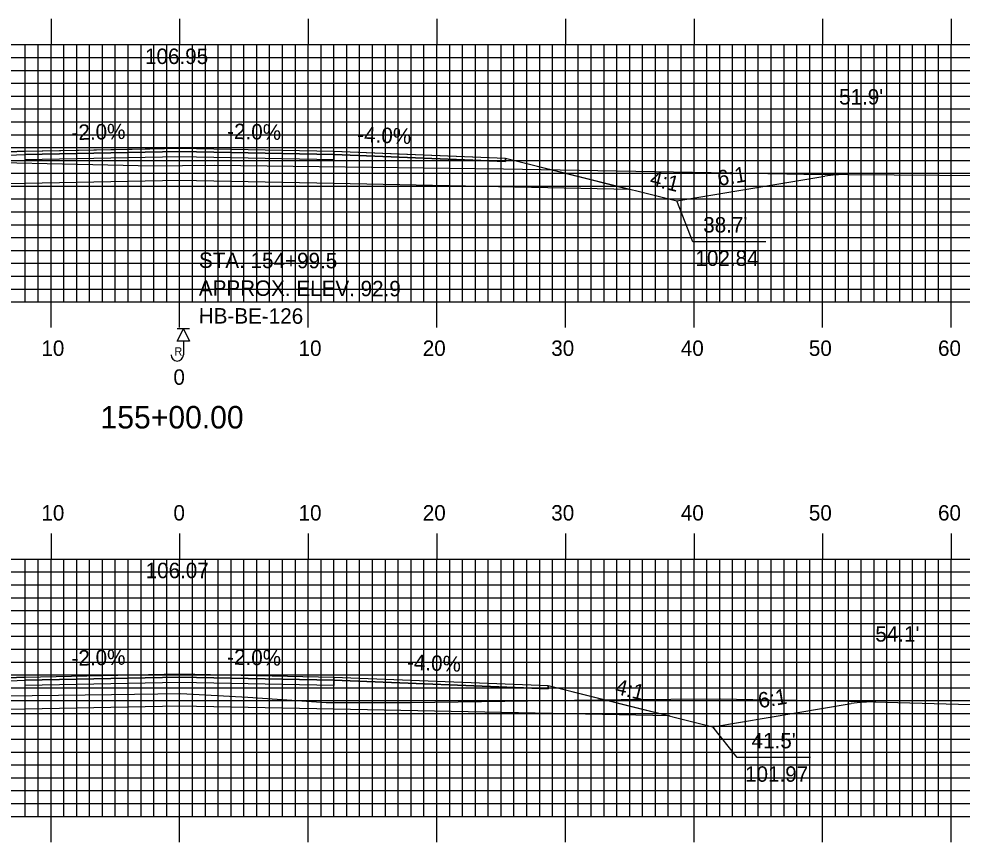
# Model space of a CAD drawing. Extents: x 1779106 to 1779449, y 442591 to 442811.
# Drawn here: x 1779258.8 to 1779332.2, y 442646.7 to 442710.7 of the extents above; entities that cross this region are included whole.
import ezdxf

# ---------------------------------------------------------------- set-up
doc = ezdxf.new("R2010")
doc.units = 0
for name, color, linetype in [('ANNOTATION', 7, 'Continuous'), ('BORING - REFUSAL', 7, 'Continuous'), ('D_Roadway_Centerline', 7, 'Continuous'), ('D_Roadway_Centerline_Text', 7, 'Continuous'), ('D_Roadway_Edge_Shoulder', 7, 'Continuous'), ('D_Roadway_Edge_TW', 7, 'Continuous'), ('D_Roadway_Pavement', 7, 'Continuous'), ('D_Roadway_SlopeLines', 7, 'Continuous'), ('D_Roadway_SubGrade', 7, 'Continuous'), ('D_Text_Standard', 7, 'Continuous'), ('H_V ANNOTATION', 7, 'Continuous'), ('MAJOR', 7, 'Continuous'), ('MINOR', 7, 'Continuous'), ('S_Roadway_Centerline', 7, 'Continuous')]:
    doc.layers.add(name, color=color, linetype=linetype)

msp = doc.modelspace()

# ---------------------------------------------------------------- linework, layer by layer
at = {"layer": 'ANNOTATION'}
for points in [[(1779316.925, 442693.332), (1779311.233, 442693.332), (1779309.983, 442696.509)], [(1779320.388, 442653.229), (1779314.696, 442653.229), (1779312.783, 442655.634)]]:
    msp.add_lwpolyline(points, dxfattribs=at)
at = {"layer": 'BORING - REFUSAL'}
for p, q in [((1779272.109, 442686.565), (1779271.149, 442686.565)), ((1779271.629, 442685.606), (1779271.629, 442684.547))]:
    msp.add_line(p, q, dxfattribs=at)
msp.add_lwpolyline([(1779271.629, 442686.565), (1779272.109, 442685.606), (1779271.149, 442685.606)], close=True, dxfattribs=at)
msp.add_arc((1779271.144, 442684.547), 0.485, 180, 0, dxfattribs=at)
at = {"layer": 'D_Roadway_Centerline'}
for points in [[(1779212.709, 442700.252), (1779213.959, 442700.189), (1779215.209, 442700.084), (1779216.459, 442699.938), (1779217.709, 442699.75), (1779219.392, 442699.47), (1779237.155, 442696.509), (1779237.6, 442696.621), (1779241.155, 442697.509), (1779251.329, 442700.052), (1779255.495, 442700.219), (1779259.329, 442700.372), (1779269.01, 442700.566), (1779271.329, 442700.612), (1779283.329, 442700.372), (1779289, 442700.145), (1779296.662, 442699.839), (1779306.371, 442697.412)], [(1779215.099, 442658.85), (1779216.348, 442658.843), (1779217.599, 442658.779), (1779217.756, 442658.764), (1779218.848, 442658.656), (1779220.098, 442658.477), (1779222.988, 442657.996), (1779237.155, 442655.634), (1779241.155, 442656.634), (1779251.329, 442659.177), (1779259.33, 442659.497), (1779271.329, 442659.737), (1779283.329, 442659.497), (1779299.996, 442658.831), (1779307.083, 442657.059), (1779309.415, 442656.476)]]:
    msp.add_lwpolyline(points, dxfattribs=at)
at = {"layer": 'D_Roadway_Edge_Shoulder'}
for points in [[(1779259.329, 442700.372), (1779251.329, 442700.052), (1779251.329, 442699.802), (1779259.329, 442700.122)], [(1779283.329, 442700.372), (1779296.662, 442699.839), (1779296.662, 442699.589), (1779283.329, 442700.122)], [(1779259.33, 442659.497), (1779251.329, 442659.177), (1779251.329, 442658.927), (1779259.33, 442659.247)], [(1779283.329, 442659.497), (1779299.996, 442658.831), (1779299.996, 442658.581), (1779283.329, 442659.247)]]:
    msp.add_lwpolyline(points, close=True, dxfattribs=at)
at = {"layer": 'D_Roadway_Edge_TW'}
for points in [[(1779259.329, 442700.122), (1779259.329, 442700.372), (1779271.329, 442700.612), (1779283.329, 442700.372), (1779283.329, 442700.122), (1779271.329, 442700.362)], [(1779259.33, 442659.247), (1779259.33, 442659.497), (1779271.329, 442659.737), (1779283.329, 442659.497), (1779283.329, 442659.247), (1779271.329, 442659.487)]]:
    msp.add_lwpolyline(points, close=True, dxfattribs=at)
at = {"layer": 'D_Roadway_Pavement'}
for points in [[(1779259.329, 442699.706), (1779259.329, 442700.122), (1779271.329, 442700.362), (1779283.329, 442700.122), (1779283.329, 442699.706), (1779271.329, 442699.946)], [(1779259.33, 442658.831), (1779259.33, 442659.247), (1779271.329, 442659.487), (1779283.329, 442659.247), (1779283.329, 442658.831), (1779271.329, 442659.071)]]:
    msp.add_lwpolyline(points, close=True, dxfattribs=at)
at = {"layer": 'D_Roadway_SlopeLines'}
msp.add_line((1779309.983, 442696.509), (1779321.501, 442698.429), dxfattribs=at)
for points in [[(1779296.662, 442699.839), (1779309.983, 442696.509)], [(1779299.996, 442658.831), (1779312.785, 442655.636)], [(1779312.783, 442655.634), (1779323.545, 442657.428)]]:
    msp.add_lwpolyline(points, dxfattribs=at)
for centre, start, end in [((1779323.145, 442688.565), 89.55743, 99.46232), ((1779325.188, 442647.564), 88.43894, 99.46085)]:
    msp.add_arc(centre, 10, start, end, dxfattribs=at)
at = {"layer": 'D_Roadway_SubGrade'}
for points in [[(1779259.329, 442697.872), (1779241.155, 442697.509), (1779251.329, 442700.052), (1779251.329, 442699.802), (1779259.329, 442700.122), (1779271.329, 442700.362), (1779283.329, 442700.122), (1779296.662, 442699.589), (1779296.662, 442699.839), (1779306.371, 442697.412), (1779283.329, 442697.872), (1779271.329, 442698.112)], [(1779259.33, 442656.997), (1779241.155, 442656.634), (1779251.329, 442659.177), (1779251.329, 442658.927), (1779259.33, 442659.247), (1779271.329, 442659.487), (1779283.329, 442659.247), (1779299.996, 442658.581), (1779299.996, 442658.831), (1779309.415, 442656.476), (1779283.329, 442656.997), (1779271.329, 442657.237)]]:
    msp.add_lwpolyline(points, close=True, dxfattribs=at)
at = {"layer": 'MAJOR'}
for p, q in [((1779261.329, 442710.669), (1779261.329, 442708.665)), ((1779271.329, 442710.669), (1779271.329, 442708.665)), ((1779281.329, 442710.669), (1779281.329, 442708.665)), ((1779291.329, 442710.669), (1779291.329, 442708.665)), ((1779301.329, 442710.669), (1779301.329, 442708.665)), ((1779311.329, 442710.669), (1779311.329, 442708.665)), ((1779321.329, 442710.669), (1779321.329, 442708.665)), ((1779331.329, 442710.669), (1779331.329, 442708.665)), ((1779131.329, 442708.665), (1779411.329, 442708.665)), ((1779131.329, 442708.665), (1779411.329, 442708.665)), ((1779261.329, 442688.665), (1779261.329, 442708.665)), ((1779271.329, 442688.665), (1779271.329, 442708.665)), ((1779281.329, 442688.665), (1779281.329, 442708.665)), ((1779291.329, 442688.665), (1779291.329, 442708.665)), ((1779301.329, 442688.665), (1779301.329, 442708.665)), ((1779311.329, 442688.665), (1779311.329, 442708.665)), ((1779321.329, 442688.665), (1779321.329, 442708.665)), ((1779331.329, 442688.665), (1779331.329, 442708.665)), ((1779131.329, 442703.665), (1779411.329, 442703.665)), ((1779131.956, 442698.665), (1779411.956, 442698.665)), ((1779131.329, 442693.665), (1779411.329, 442693.665)), ((1779131.329, 442688.665), (1779411.329, 442688.665)), ((1779131.329, 442688.665), (1779411.329, 442688.665)), ((1779261.329, 442686.661), (1779261.329, 442688.665)), ((1779271.329, 442686.661), (1779271.329, 442688.665)), ((1779281.329, 442686.661), (1779281.329, 442688.665)), ((1779291.329, 442686.661), (1779291.329, 442688.665)), ((1779301.329, 442686.661), (1779301.329, 442688.665)), ((1779311.329, 442686.661), (1779311.329, 442688.665)), ((1779321.329, 442686.661), (1779321.329, 442688.665)), ((1779331.329, 442686.661), (1779331.329, 442688.665)), ((1779261.329, 442670.669), (1779261.329, 442668.665)), ((1779271.329, 442670.669), (1779271.329, 442668.665)), ((1779281.329, 442670.669), (1779281.329, 442668.665)), ((1779291.329, 442670.669), (1779291.329, 442668.665)), ((1779301.329, 442670.669), (1779301.329, 442668.665)), ((1779311.329, 442670.669), (1779311.329, 442668.665)), ((1779321.329, 442670.669), (1779321.329, 442668.665)), ((1779331.329, 442670.669), (1779331.329, 442668.665)), ((1779131.329, 442668.665), (1779411.329, 442668.665)), ((1779131.329, 442668.665), (1779411.329, 442668.665)), ((1779261.329, 442648.665), (1779261.329, 442668.665)), ((1779271.329, 442648.665), (1779271.329, 442668.665)), ((1779281.329, 442648.665), (1779281.329, 442668.665)), ((1779291.329, 442648.665), (1779291.329, 442668.665)), ((1779301.329, 442648.665), (1779301.329, 442668.665)), ((1779311.329, 442648.665), (1779311.329, 442668.665)), ((1779321.329, 442648.665), (1779321.329, 442668.665)), ((1779331.329, 442648.665), (1779331.329, 442668.665)), ((1779131.329, 442663.665), (1779411.329, 442663.665)), ((1779131.329, 442658.665), (1779411.329, 442658.665)), ((1779131.329, 442653.665), (1779411.329, 442653.665)), ((1779131.329, 442648.665), (1779411.329, 442648.665)), ((1779131.329, 442648.665), (1779411.329, 442648.665)), ((1779261.329, 442646.661), (1779261.329, 442648.665)), ((1779271.329, 442646.661), (1779271.329, 442648.665)), ((1779281.329, 442646.661), (1779281.329, 442648.665)), ((1779291.329, 442646.661), (1779291.329, 442648.665)), ((1779301.329, 442646.661), (1779301.329, 442648.665)), ((1779311.329, 442646.661), (1779311.329, 442648.665)), ((1779321.329, 442646.661), (1779321.329, 442648.665)), ((1779331.329, 442646.661), (1779331.329, 442648.665))]:
    msp.add_line(p, q, dxfattribs=at)
at = {"layer": 'MINOR'}
for p, q in [((1779259.329, 442688.665), (1779259.329, 442708.665)), ((1779260.329, 442688.665), (1779260.329, 442708.665)), ((1779262.329, 442688.665), (1779262.329, 442708.665)), ((1779263.329, 442688.665), (1779263.329, 442708.665)), ((1779264.329, 442688.665), (1779264.329, 442708.665)), ((1779265.329, 442688.665), (1779265.329, 442708.665)), ((1779266.329, 442688.665), (1779266.329, 442708.665)), ((1779267.329, 442688.665), (1779267.329, 442708.665)), ((1779268.329, 442688.665), (1779268.329, 442708.665)), ((1779269.329, 442688.665), (1779269.329, 442708.665)), ((1779270.329, 442688.665), (1779270.329, 442708.665)), ((1779272.329, 442688.665), (1779272.329, 442708.665)), ((1779273.329, 442688.665), (1779273.329, 442708.665)), ((1779274.329, 442688.665), (1779274.329, 442708.665)), ((1779275.329, 442688.665), (1779275.329, 442708.665)), ((1779276.329, 442688.665), (1779276.329, 442708.665)), ((1779277.329, 442688.665), (1779277.329, 442708.665)), ((1779278.329, 442688.665), (1779278.329, 442708.665)), ((1779279.329, 442688.665), (1779279.329, 442708.665)), ((1779280.329, 442688.665), (1779280.329, 442708.665)), ((1779282.329, 442688.665), (1779282.329, 442708.665)), ((1779283.329, 442688.665), (1779283.329, 442708.665)), ((1779284.329, 442688.665), (1779284.329, 442708.665)), ((1779285.329, 442688.665), (1779285.329, 442708.665)), ((1779286.329, 442688.665), (1779286.329, 442708.665)), ((1779287.329, 442688.665), (1779287.329, 442708.665)), ((1779288.329, 442688.665), (1779288.329, 442708.665)), ((1779289.329, 442688.665), (1779289.329, 442708.665)), ((1779290.329, 442688.665), (1779290.329, 442708.665)), ((1779292.329, 442688.665), (1779292.329, 442708.665)), ((1779293.329, 442688.665), (1779293.329, 442708.665)), ((1779294.329, 442688.665), (1779294.329, 442708.665)), ((1779295.329, 442688.665), (1779295.329, 442708.665)), ((1779296.329, 442688.665), (1779296.329, 442708.665)), ((1779297.329, 442688.665), (1779297.329, 442708.665)), ((1779298.329, 442688.665), (1779298.329, 442708.665)), ((1779299.329, 442688.665), (1779299.329, 442708.665)), ((1779300.329, 442688.665), (1779300.329, 442708.665)), ((1779302.329, 442688.665), (1779302.329, 442708.665)), ((1779303.329, 442688.665), (1779303.329, 442708.665)), ((1779304.329, 442688.665), (1779304.329, 442708.665)), ((1779305.329, 442688.665), (1779305.329, 442708.665)), ((1779306.329, 442688.665), (1779306.329, 442708.665)), ((1779307.329, 442688.665), (1779307.329, 442708.665)), ((1779308.329, 442688.665), (1779308.329, 442708.665)), ((1779309.329, 442688.665), (1779309.329, 442708.665)), ((1779310.329, 442688.665), (1779310.329, 442708.665)), ((1779312.329, 442688.665), (1779312.329, 442708.665)), ((1779313.329, 442688.665), (1779313.329, 442708.665)), ((1779314.329, 442688.665), (1779314.329, 442708.665)), ((1779315.329, 442688.665), (1779315.329, 442708.665)), ((1779316.329, 442688.665), (1779316.329, 442708.665)), ((1779317.329, 442688.665), (1779317.329, 442708.665)), ((1779318.329, 442688.665), (1779318.329, 442708.665)), ((1779319.329, 442688.665), (1779319.329, 442708.665)), ((1779320.329, 442688.665), (1779320.329, 442708.665)), ((1779322.329, 442688.665), (1779322.329, 442708.665)), ((1779323.329, 442688.665), (1779323.329, 442708.665)), ((1779324.329, 442688.665), (1779324.329, 442708.665)), ((1779325.329, 442688.665), (1779325.329, 442708.665)), ((1779326.329, 442688.665), (1779326.329, 442708.665)), ((1779327.329, 442688.665), (1779327.329, 442708.665)), ((1779328.329, 442688.665), (1779328.329, 442708.665)), ((1779329.329, 442688.665), (1779329.329, 442708.665)), ((1779330.329, 442688.665), (1779330.329, 442708.665)), ((1779131.329, 442707.665), (1779411.329, 442707.665)), ((1779131.329, 442706.665), (1779411.329, 442706.665)), ((1779131.329, 442705.665), (1779411.329, 442705.665)), ((1779131.329, 442704.665), (1779411.329, 442704.665)), ((1779131.329, 442702.665), (1779411.329, 442702.665)), ((1779131.329, 442701.665), (1779411.329, 442701.665)), ((1779131.329, 442700.665), (1779411.329, 442700.665)), ((1779131.329, 442699.665), (1779411.329, 442699.665)), ((1779131.329, 442697.665), (1779411.329, 442697.665)), ((1779131.329, 442696.665), (1779411.329, 442696.665)), ((1779131.329, 442695.665), (1779411.329, 442695.665)), ((1779131.329, 442694.665), (1779411.329, 442694.665)), ((1779131.329, 442692.665), (1779411.329, 442692.665)), ((1779131.329, 442691.665), (1779411.329, 442691.665)), ((1779131.329, 442690.665), (1779411.329, 442690.665)), ((1779131.329, 442689.665), (1779411.329, 442689.665)), ((1779259.329, 442648.665), (1779259.329, 442668.665)), ((1779260.329, 442648.665), (1779260.329, 442668.665)), ((1779262.329, 442648.665), (1779262.329, 442668.665)), ((1779263.329, 442648.665), (1779263.329, 442668.665)), ((1779264.329, 442648.665), (1779264.329, 442668.665)), ((1779265.329, 442648.665), (1779265.329, 442668.665)), ((1779266.329, 442648.665), (1779266.329, 442668.665)), ((1779267.329, 442648.665), (1779267.329, 442668.665)), ((1779268.329, 442648.665), (1779268.329, 442668.665)), ((1779269.329, 442648.665), (1779269.329, 442668.665)), ((1779270.329, 442648.665), (1779270.329, 442668.665)), ((1779272.329, 442648.665), (1779272.329, 442668.665)), ((1779273.329, 442648.665), (1779273.329, 442668.665)), ((1779274.329, 442648.665), (1779274.329, 442668.665)), ((1779275.329, 442648.665), (1779275.329, 442668.665)), ((1779276.329, 442648.665), (1779276.329, 442668.665)), ((1779277.329, 442648.665), (1779277.329, 442668.665)), ((1779278.329, 442648.665), (1779278.329, 442668.665)), ((1779279.329, 442648.665), (1779279.329, 442668.665)), ((1779280.329, 442648.665), (1779280.329, 442668.665)), ((1779282.329, 442648.665), (1779282.329, 442668.665)), ((1779283.329, 442648.665), (1779283.329, 442668.665)), ((1779284.329, 442648.665), (1779284.329, 442668.665)), ((1779285.329, 442648.665), (1779285.329, 442668.665)), ((1779286.329, 442648.665), (1779286.329, 442668.665)), ((1779287.329, 442648.665), (1779287.329, 442668.665)), ((1779288.329, 442648.665), (1779288.329, 442668.665)), ((1779289.329, 442648.665), (1779289.329, 442668.665)), ((1779290.329, 442648.665), (1779290.329, 442668.665)), ((1779292.329, 442648.665), (1779292.329, 442668.665)), ((1779293.329, 442648.665), (1779293.329, 442668.665)), ((1779294.329, 442648.665), (1779294.329, 442668.665)), ((1779295.329, 442648.665), (1779295.329, 442668.665)), ((1779296.329, 442648.665), (1779296.329, 442668.665)), ((1779297.329, 442648.665), (1779297.329, 442668.665)), ((1779298.329, 442648.665), (1779298.329, 442668.665)), ((1779299.329, 442648.665), (1779299.329, 442668.665)), ((1779300.329, 442648.665), (1779300.329, 442668.665)), ((1779302.329, 442648.665), (1779302.329, 442668.665)), ((1779303.329, 442648.665), (1779303.329, 442668.665)), ((1779304.329, 442648.665), (1779304.329, 442668.665)), ((1779305.329, 442648.665), (1779305.329, 442668.665)), ((1779306.329, 442648.665), (1779306.329, 442668.665)), ((1779307.329, 442648.665), (1779307.329, 442668.665)), ((1779308.329, 442648.665), (1779308.329, 442668.665)), ((1779309.329, 442648.665), (1779309.329, 442668.665)), ((1779310.329, 442648.665), (1779310.329, 442668.665)), ((1779312.329, 442648.665), (1779312.329, 442668.665)), ((1779313.329, 442648.665), (1779313.329, 442668.665)), ((1779314.329, 442648.665), (1779314.329, 442668.665)), ((1779315.329, 442648.665), (1779315.329, 442668.665)), ((1779316.329, 442648.665), (1779316.329, 442668.665)), ((1779317.329, 442648.665), (1779317.329, 442668.665)), ((1779318.329, 442648.665), (1779318.329, 442668.665)), ((1779319.329, 442648.665), (1779319.329, 442668.665)), ((1779320.329, 442648.665), (1779320.329, 442668.665)), ((1779322.329, 442648.665), (1779322.329, 442668.665)), ((1779323.329, 442648.665), (1779323.329, 442668.665)), ((1779324.329, 442648.665), (1779324.329, 442668.665)), ((1779325.329, 442648.665), (1779325.329, 442668.665)), ((1779326.329, 442648.665), (1779326.329, 442668.665)), ((1779327.329, 442648.665), (1779327.329, 442668.665)), ((1779328.329, 442648.665), (1779328.329, 442668.665)), ((1779329.329, 442648.665), (1779329.329, 442668.665)), ((1779330.329, 442648.665), (1779330.329, 442668.665)), ((1779131.329, 442667.665), (1779411.329, 442667.665)), ((1779131.329, 442666.665), (1779411.329, 442666.665)), ((1779131.329, 442665.665), (1779411.329, 442665.665)), ((1779131.329, 442664.665), (1779411.329, 442664.665)), ((1779131.329, 442662.665), (1779411.329, 442662.665)), ((1779131.329, 442661.665), (1779411.329, 442661.665)), ((1779131.329, 442660.665), (1779411.329, 442660.665)), ((1779131.329, 442659.665), (1779411.329, 442659.665)), ((1779131.329, 442657.665), (1779411.329, 442657.665)), ((1779131.329, 442656.665), (1779411.329, 442656.665)), ((1779131.329, 442655.665), (1779411.329, 442655.665)), ((1779131.329, 442654.665), (1779411.329, 442654.665)), ((1779131.329, 442652.665), (1779411.329, 442652.665)), ((1779131.329, 442651.665), (1779411.329, 442651.665)), ((1779131.329, 442650.665), (1779411.329, 442650.665)), ((1779131.329, 442649.665), (1779411.329, 442649.665))]:
    msp.add_line(p, q, dxfattribs=at)
at = {"layer": 'S_Roadway_Centerline'}
for points in [[(1779204.871, 442700.576), (1779214.722, 442700.169), (1779223.429, 442700.124), (1779228.785, 442700.064), (1779247.046, 442699.731), (1779248.885, 442699.733), (1779250.388, 442699.649), (1779269.305, 442699.254), (1779271.551, 442699.27), (1779274.069, 442699.291), (1779294.366, 442699.041), (1779296.506, 442699.002), (1779318.544, 442698.617), (1779319.857, 442698.591), (1779340.931, 442698.428)], [(1779190.733, 442658.669), (1779209.659, 442658.921), (1779213.36, 442658.816), (1779217.296, 442658.895), (1779225.136, 442658.872), (1779231.553, 442658.528), (1779242.659, 442658.056), (1779248.767, 442658.064), (1779253.673, 442657.985), (1779266.039, 442658.147), (1779271.426, 442658.224), (1779276.627, 442657.928), (1779282.717, 442657.528), (1779289.372, 442657.506), (1779305.664, 442657.756), (1779313.385, 442657.809), (1779317.147, 442657.713), (1779321.517, 442657.667), (1779341.306, 442657.128)]]:
    msp.add_lwpolyline(points, dxfattribs=at)

# ---------------------------------------------------------------- texts
at = {"layer": 'ANNOTATION'}
for s, rotation, p in [('-2.0%', 1.14576, (1779262.935, 442701.245)), ('-2.0%', 358.85424, (1779275.015, 442701.339)), ('-4.0%', 357.70926, (1779285.121, 442701.102)), ('6:1', 9.46012, (1779313.259, 442697.669)), ('4:1', 345.96306, (1779307.824, 442697.75)), ('-2.0%', 1.14582, (1779262.936, 442660.37)), ('-2.0%', 358.85424, (1779275.015, 442660.464)), ('-4.0%', 357.70947, (1779288.993, 442660.072)), ('4:1', 345.96523, (1779305.125, 442658.215)), ('6:1', 9.46087, (1779316.421, 442657.068))]:
    msp.add_text(s, height=1.2, rotation=rotation, dxfattribs=at).set_placement(p)
for s, p in [("38.7'", (1779312.043, 442694.059)), ('102.84', (1779311.438, 442691.459)), ("41.5'", (1779315.805, 442653.955)), ('101.97', (1779315.297, 442651.355))]:
    msp.add_text(s, height=1.2, dxfattribs=at).set_placement(p)
at = {"layer": 'BORING - REFUSAL'}
for s, p in [('STA. 154+99.5', (1779272.833, 442691.308)), ('APPROX. ELEV. 92.9', (1779272.826, 442689.148)), ('HB-BE-126', (1779272.819, 442686.988))]:
    msp.add_text(s, height=1.2, rotation=359.81416, dxfattribs=at).set_placement(p)
msp.add_text('R', height=0.64, dxfattribs=at).set_placement((1779270.92, 442684.491))
at = {"layer": 'D_Roadway_Centerline'}
for s, p in [('C', (1779271.324, 442700.612)), ('L', (1779271.329, 442700.605)), ('C', (1779271.324, 442659.737)), ('L', (1779271.329, 442659.73))]:
    msp.add_text(s, height=0.0146, dxfattribs=at).set_placement(p)
at = {"layer": 'D_Roadway_Centerline_Text'}
for s, p in [('106.95', (1779268.638, 442707.159)), ('106.07', (1779268.686, 442667.184))]:
    msp.add_text(s, height=1.2, dxfattribs=at).set_placement(p)
at = {"layer": 'D_Text_Standard'}
for s, p in [("51.9'", (1779322.609, 442704.01)), ("54.1'", (1779325.425, 442662.251))]:
    msp.add_text(s, height=1.2, dxfattribs=at).set_placement(p)
at = {"layer": 'H_V ANNOTATION'}
for s, height, p in [('10', 1.2, (1779260.58, 442684.465)), ('10', 1.2, (1779280.58, 442684.465)), ('20', 1.2, (1779290.237, 442684.465)), ('30', 1.2, (1779300.227, 442684.465)), ('40', 1.2, (1779310.301, 442684.465)), ('50', 1.2, (1779320.258, 442684.465)), ('60', 1.2, (1779330.301, 442684.465)), ('0', 1.2, (1779270.847, 442682.218)), ('155+00.00', 1.75, (1779265.18, 442678.821)), ('10', 1.2, (1779260.58, 442671.665)), ('0', 1.2, (1779270.847, 442671.665)), ('10', 1.2, (1779280.58, 442671.665)), ('20', 1.2, (1779290.237, 442671.665)), ('30', 1.2, (1779300.227, 442671.665)), ('40', 1.2, (1779310.301, 442671.665)), ('50', 1.2, (1779320.258, 442671.665)), ('60', 1.2, (1779330.301, 442671.665))]:
    msp.add_text(s, height=height, dxfattribs=at).set_placement(p)

doc.saveas('drawing.dxf')
